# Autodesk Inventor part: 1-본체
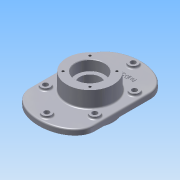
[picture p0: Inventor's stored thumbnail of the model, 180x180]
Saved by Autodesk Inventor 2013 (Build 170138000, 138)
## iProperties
Created: 2015-02
Part Number: 1-본체
Material: 알루미늄 6061
Document SubType Name: Modeling
Designer: Administrator
Density: 2.40731 g/cm^3
Mass: 1476 g
Surface Area: 943.341 cm^2
Volume: 613.132 cm^3
Author: Administrator
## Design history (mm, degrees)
sketch "스케치1"
  geometry: L1 (70, -60)-(-70, -60); L2 (-70, -60)-(-70, 60); L3 (-70, 60)-(70, 60); L4 (70, 60)-(70, -60); L5 (70, -60)-(-70, 60); L6 (-70, -60)-(70, 60); 7 further points; 2 other entities
  constraints: 12 end point, 4 midpoint, 3 horizontal, 2 coincident, 2 parallel, 2 vertical alignment, 1 perpendicular, 8 other
  dimensions: "d0" = 140 distance of L1.start L1.end; "d2" = 120 distance of L3.end L1.start; "d3" = 50 distance from line of point (0, 110) L3; "d4" = 50 distance from line of point (0, -110) L1
extrude "돌출1" new body sketch "스케치1" distance "d5" = 12; taper "d6" = 0 deg
sketch "스케치2"
  geometry: L1 (-70, 60)-(-70, -60) reference; L2 (70, -60)-(70, 60) reference; L3 (-53, 60)-(-53, -60); L4 (53, -60)-(53, 60); C1 r 10 at (53, 42.733); C2 r 10 at (53, -42.733); C3 r 10 at (0, 93); C4 r 10 at (0, -93); 3 further points; 2 other entities
  constraints: 4 centre point, 4 end point, 3 parallel, 2 equal radius, 2 point on line, 2 vertical alignment, 10 other
  dimensions: "d7" = 17 distance between parallel lines of L2 L4; "d8" = 85.46667 distance of C2.centre C1.centre; "d9" = 42.73333 vertical distance of C2.centre point (0, 0); "d10" = 20 diameter of C1; "d13" = 20 diameter of C3
extrude "돌출2" join sketch "스케치2" distance "d11" = 5; taper "d12" = 0 deg
extrude "돌출3" join sketch "스케치2" distance "d14" = 5; taper "d15" = 0 deg
node "작업 평면1"
sketch "스케치4"
  geometry: C1 r 50 at (0, 0); 1 further point
  constraints: 1 centre point, 1 coincident
  dimensions: "d17" = 100 diameter of C1
extrude "돌출4" join sketch "스케치4" distance "d19" = 70; taper "d20" = 0 deg
sketch "스케치5"
  geometry: C1 r 50 at (0, 0) reference; 1 further point
  constraints: 1 coincident
hole "구멍1" sketch "스케치5" at (0, 0) diameter "d21" = 45; stored, may be unused: countersink angle "d25" = 90 deg, drill point angle "d27" = 118 deg; dims "d22" = 6, "d23" = 62, "d24" = 22, "d26" = 8
hole "구멍2" diameter "d30" = 62; stored, may be unused: countersink angle "d34" = 90 deg, drill point angle "d36" = 0 deg; dims "d28" = 10, "d29" = 10, "d31" = 6, "d32" = 62, "d33" = 22, "d35" = 22
sketch "스케치6"
  geometry: C1 r 31 at (0, 0) reference; C2 r 50 at (0, 0) reference; A1 r 41 centre (0, 0) between (-28.991, 28.991) and (0, 41)
  constraints: 2 point on circle, 1 centre point, 1 coincident, 1 vertical alignment
  dimensions: "d37" = 82 diameter of A1; "d39" = 45 deg dimension on C1.centre A1.start A1.end
hole "구멍3" sketch "스케치6" at (-28.991, 28.991) diameter "d41" = 5.134; stored, may be unused: countersink angle "d45" = 90 deg, drill point angle "d47" = 118 deg; dims "d42" = 10, "d43" = 62, "d44" = 22, "d46" = 13
node "작업 평면2"
sketch "스케치7"
  geometry: C1 r 10 at (0, 0) reference; C2 r 10 at (-53, -50.267) reference; C3 r 10 at (53, -50.267) reference; C4 r 10 at (-53, -135.733) reference; C5 r 10 at (0, -186) reference; C6 r 10 at (53, -135.733) reference; 7 further points
  constraints: 6 coincident
hole "구멍4" sketch "스케치7" at (0, 0), (-53, -50.267), (53, -50.267), (53, -135.733), (-53, -135.733), (0, -186) diameter "d51" = 11; stored, may be unused: countersink angle "d55" = 90 deg, drill point angle "d57" = 0 deg; dims "d52" = 10, "d53" = 62, "d54" = 22, "d56" = 13
sketch "스케치8"
  geometry: C1 r 50 at (0, 0) reference; 1 further point
  constraints: 1 vertical alignment, 1 other
  dimensions: "d58" = 65 distance of C1.centre point (0, 65)
feature "엠보싱1" sketch "스케치8" dims "d0" = 140, "d2" = 120, "d3" = 50, "d4" = 50, "d59" = 1, "d60" = 0
fillet "모깎기1" dims "d61" = 3
fillet "모깎기2" dims "d62" = 0.3
fillet "모깎기3" dims "d63" = 3
chamfer "모따기1" distance "d64" = 1; stored, may be unused: second distance "d65" = 2, angle "d66" = 45 deg
node "솔리드1"
mirror "대칭1"
pattern_circular "원형 패턴1" dims angle "d49" = 360 deg
mirror "대칭2"
node "투영된 루프1"
node "투영된 루프2"
node "투영된 루프3"
node "투영된 루프4"
node "투영된 루프5"
other parameters: "d16" = 23
